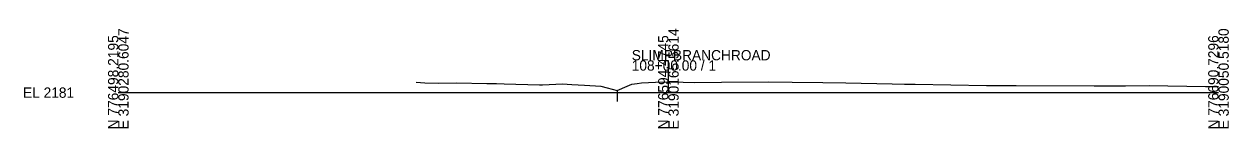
# Model space of a CAD drawing. Extents: x -26 to 303, y -10 to 13517.
# Drawn here: x -25.7 to 302.8, y 13490.3 to 13517.4 of the extents above; entities that cross this region are included whole.
import ezdxf

# ---------------------------------------------------------------- set-up
doc = ezdxf.new("R2010")
doc.units = 0
for name, color, linetype in [('DESIGN - SHEET - Light Grid', 7, 'Continuous'), ('DESIGN - TYPICAL - Finished Grade and Subgrade', 7, 'Continuous'), ('SURVEY - GROUND - Top of Ground', 7, 'Continuous')]:
    doc.layers.add(name, color=color, linetype=linetype)

msp = doc.modelspace()

# ---------------------------------------------------------------- linework, layer by layer
at = {"layer": 'DESIGN - SHEET - Light Grid'}
for p, q in [((150, 13500), (150, 13508.78)), ((0, 13500), (150, 13500)), ((150, 13500), (300, 13500))]:
    msp.add_line(p, q, dxfattribs=at)
at = {"layer": 'DESIGN - TYPICAL - Finished Grade and Subgrade'}
msp.add_line((136.02, 13500.62), (136.02, 13497.62), dxfattribs=at)
at = {"layer": 'SURVEY - GROUND - Top of Ground'}
msp.add_lwpolyline([(81.21, 13502.86), (83.56, 13502.64), (87.27, 13502.56), (92.23, 13502.66), (100.47, 13502.47), (103.09, 13502.44), (105.25, 13502.43), (114.89, 13502.15), (115.65, 13502.15), (121.16, 13502.41), (123.65, 13502.24), (127.08, 13502.05), (131.61, 13501.8), (133.31, 13501.32), (136.02, 13500.62), (138.76, 13501.71), (140, 13502.3), (141.46, 13502.46), (142.7, 13502.66), (146.44, 13502.8), (149.9, 13502.93), (154.01, 13502.88), (157.23, 13502.77), (164.45, 13502.87), (177.4, 13502.92), (183.76, 13502.87), (192.1, 13502.77), (198.36, 13502.69), (211.03, 13502.36), (214.34, 13502.28), (217.33, 13502.26), (236.77, 13501.98), (240.3, 13501.96), (244.86, 13501.91), (266.1, 13501.84), (274.64, 13501.88), (281.07, 13501.93), (296.44, 13501.68), (300, 13501.66)], dxfattribs=at)

# ---------------------------------------------------------------- texts
at = {"layer": 'DESIGN - SHEET - Light Grid'}
for s, p in [('E 3190280.6047', (2.8, 13490)), ('E 3190165.5614', (152.8, 13490)), ('E 3190050.5180', (302.8, 13490)), ('N 776498.2195', (0, 13490)), ('N 776594.4745', (150, 13490)), ('N 776690.7296', (300, 13490))]:
    msp.add_text(s, height=2.8, rotation=90, dxfattribs=at).set_placement(p)
for s, p in [('SLIMPBRANCHROAD', (140, 13508.78)), ('108+00.00 / 1', (140, 13505.98)), ('EL 2181', (-26, 13498.6))]:
    msp.add_text(s, height=2.8, dxfattribs=at).set_placement(p)

doc.saveas('drawing.dxf')
